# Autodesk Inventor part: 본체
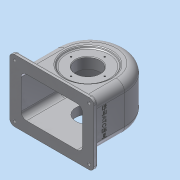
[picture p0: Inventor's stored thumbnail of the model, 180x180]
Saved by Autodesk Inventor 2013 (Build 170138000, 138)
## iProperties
Created: 2016-01
Part Number: 본체
Material: 알루미늄 6061
Document SubType Name: Modeling
Designer: Administrator
Density: 2.71 g/cm^3
Mass: 827.356 g
Surface Area: 1006.17 cm^2
Volume: 305.298 cm^3
Author: Administrator
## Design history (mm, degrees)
sketch "스케치1"
  geometry: L1 (-70, -53)-(70, -53); L2 (70, -53)-(70, -60); L3 (70, -60)-(-70, -60); L4 (-70, -60)-(-70, -53); L5 (-70, -53)-(70, -60); L6 (70, -53)-(-70, -60); L7 (-57, 4)-(-57, -53); L8 (57, 4)-(57, -53); C1 r 51 at (0, 4); A1 r 57 centre (0, 4) between (57, 4) and (-57, 4); 3 further points
  constraints: 16 end point, 3 midpoint, 3 parallel, 2 centre point, 2 perpendicular, 2 point on circle, 2 point on line, 2 tangent, 2 vertical alignment, 1 horizontal
  dimensions: "d0" = 140 distance of L2.end L3.end; "d1" = 7 distance of L1.end L2.end; "d2" = 60 distance from line of point (0, 0) L3; "d3" = 102 diameter of C1; "d4" = 64 distance from line of L3 C1.centre; "d6" = 6 radial gap between concentric circles of C1 A1
extrude "돌출1" new body sketch "스케치1" stored distance "d7" = 77; taper "d8" = 0 deg
extrude "돌출2" join sketch "스케치1" stored distance "d9" = 104; taper "d10" = 0 deg
feature "쉘1" dims "d11" = 6, "d12" = 5
sketch "스케치2"
  geometry: L1 (57, -38.5)-(-57, -38.5) reference; L2 (-57, -38.5)-(-57, 38.5) reference; L3 (-57, 38.5)-(57, 38.5) reference; L4 (57, 38.5)-(57, -38.5) reference; L5 (-51, 33.5)-(-51, -33.5) reference; L6 (-51, -33.5)-(51, -33.5) reference; L7 (51, -33.5)-(51, 33.5) reference; L8 (51, 33.5)-(-51, 33.5) reference; L9 (-51, 33.5)-(51, 33.5); L10 (51, 33.5)-(51, -33.5); L11 (51, -33.5)-(-51, -33.5); L12 (-51, -33.5)-(-51, 33.5); 1 further point
  constraints: 8 end point, 2 parallel, 1 horizontal, 1 perpendicular
extrude "돌출3" cut sketch "스케치2" stored distance "d13" = 10; taper "d14" = 0 deg
sketch "스케치3"
  geometry: C1 r 31 at (0, 0); 1 further point
  constraints: 1 centre point, 1 coincident
  dimensions: "d15" = 62 diameter of C1
extrude "돌출4" join sketch "스케치3" distance "d16" = 10; taper "d17" = 0 deg
hole "구멍1" diameter "d20" = 40; stored, may be unused: countersink angle "d24" = 90 deg, drill point angle "d26" = 0 deg; dims "d18" = 10, "d19" = 10, "d21" = 6, "d22" = 4, "d23" = 2, "d25" = 15
chamfer "모따기1" distance "d27" = 1; stored, may be unused: second distance "d28" = 2, angle "d29" = 45 deg
sketch "스케치4" dims "d30" = 48
  geometry: C1 r 31 at (0, 0) reference; C2 r 21 at (0, 0) reference; 2 further points
  constraints: 2 vertical alignment, 1 coincident, 2 other
hole "구멍2" sketch "스케치4" at (0, 24) diameter "d31" = 2.459; stored, may be unused: countersink angle "d35" = 90 deg, drill point angle "d37" = 118 deg; dims "d32" = 6, "d33" = 4, "d34" = 2, "d36" = 8
fillet "모깎기1" dims "d41" = 14
fillet "모깎기2" dims "d42" = 9
node "작업 평면1"
sketch "스케치5"
  geometry: C1 r 6 at (0, 0); 1 further point
  constraints: 1 centre point, 1 coincident
  dimensions: "d44" = 12 diameter of C1
extrude "돌출5" join sketch "스케치5" stored distance "d45" = 10; taper "d46" = 0 deg
fillet "모깎기3" dims "d47" = 3
hole "구멍3" diameter "d50" = 4.459; stored, may be unused: countersink angle "d54" = 90 deg, drill point angle "d56" = 118 deg; dims "d48" = 10, "d49" = 10, "d51" = 6, "d52" = 4, "d53" = 2, "d55" = 8
fillet "모깎기4" dims "d57" = 8
fillet "모깎기5" dims "d58" = 3
sketch "스케치6"
  geometry: 3 further points
  dimensions: "d59" = 44 vertical distance of point (62, -49) point (0, -5); "d60" = 62 horizontal distance of point (62, -49) point (0, -5); "d61" = 124 distance of point (124, -5) point (0, -5); "d62" = 44 vertical distance of point (124, -5) point (62, -49)
hole "구멍4" sketch "스케치6" at (0, -5), (124, -5) diameter "d63" = 5; stored, may be unused: countersink angle "d67" = 90 deg, drill point angle "d69" = 0 deg; dims "d64" = 6, "d65" = 4, "d66" = 2, "d68" = 7
node "작업 평면2"
sketch "스케치7"
  geometry: C1 r 28 at (0, -4); 1 further point
  constraints: 1 centre point, 1 coincident
  dimensions: "d74" = 56 diameter of C1
extrude "돌출6" join sketch "스케치7" stored distance "d75" = 10; taper "d76" = 40 deg
fillet "모깎기6" dims "d77" = 3
sketch "스케치8"
  geometry: L1 (64, 6)-(67, 6) reference; L2 (67, 6)-(67, 2.229) reference; L3 (67, 2.229)-(55, 2.229) reference; L4 (55, 2.229)-(55, 24.5) reference; L5 (46, 33.5)-(41.426, 33.5) reference; L6 (41.426, 33.5)-(28, 17.5) reference; L7 (28, 17.5)-(-28, 17.5) reference; L8 (-28, 17.5)-(-41.426, 33.5) reference; L9 (-41.426, 33.5)-(-60, 33.5) reference; L10 (-60, 33.5)-(-60, 52) reference; L11 (-60, 52)-(-56, 52) reference; L12 (-53, 49)-(-53, 38.5) reference; L13 (-53, 38.5)-(47, 38.5) reference; L14 (61, 24.5)-(61, 9) reference; L15 (-20, -47.5)-(-21, -48.5) reference; L16 (-21, -48.5)-(-22.771, -48.5) reference; L17 (-22.771, -48.5)-(-22.771, -40.5) reference; L18 (-22.771, -40.5)-(-24, -39.761) reference; L19 (-24, -39.761)-(-25.23, -40.5) reference; L20 (-25.23, -40.5)-(-25.23, -48.5) reference; L21 (-25.23, -48.5)-(-31, -48.5) reference; L22 (-31, -48.5)-(-31, -41.5) reference; L23 (-34, -38.5)-(-53, -38.5) reference; L24 (-53, -38.5)-(-53, -49) reference; L25 (-56, -52)-(-60, -52) reference; L26 (-60, -52)-(-60, -33.5) reference; L27 (-60, -33.5)-(-20, -33.5) reference; L28 (-20, -33.5)-(-20, -47.5) reference; L29 (21, -48.5)-(20, -47.5) reference; L30 (20, -47.5)-(20, -33.5) reference; L31 (20, -33.5)-(46, -33.5) reference; L32 (55, -24.5)-(55, -2.229) reference; L33 (55, -2.229)-(67, -2.229) reference; L34 (67, -2.229)-(67, -6) reference; L35 (67, -6)-(64, -6) reference; L36 (61, -9)-(61, -24.5) reference; L37 (47, -38.5)-(34, -38.5) reference; L38 (31, -41.5)-(31, -48.5) reference; L39 (31, -48.5)-(25.23, -48.5) reference; L40 (25.23, -48.5)-(25.23, -40.5) reference; L41 (25.23, -40.5)-(24, -39.761) reference; L42 (24, -39.761)-(22.771, -40.5) reference; L43 (22.771, -40.5)-(22.771, -48.5) reference; L44 (22.771, -48.5)-(21, -48.5) reference; L45 (39.094, 38.5)-(36.577, 35.5); L46 (36.577, 35.5)-(0, 35.5); L47 (39.094, 38.5)-(0, 38.5); L48 (0, 38.5)-(0, 35.5); A1 r 9 centre (46, 24.5) between (55, 24.5) and (46, 33.5) reference; A2 r 3 centre (-56, 49) between (-53, 49) and (-56, 52) reference; A3 r 14 centre (47, 24.5) between (61, 24.5) and (47, 38.5) reference; A4 r 3 centre (-34, -41.5) between (-31, -41.5) and (-34, -38.5) reference; A5 r 3 centre (-56, -49) between (-56, -52) and (-53, -49) reference; A6 r 9 centre (46, -24.5) between (46, -33.5) and (55, -24.5) reference; A7 r 14 centre (47, -24.5) between (47, -38.5) and (61, -24.5) reference; A8 r 3 centre (34, -41.5) between (34, -38.5) and (31, -41.5) reference; 2 further points
  constraints: 8 end point, 2 parallel, 2 point on line, 1 midpoint, 1 perpendicular, 1 vertical alignment, 2 other
  dimensions: "d78" = 5 distance between parallel lines of L45 L6; "d79" = 3 distance between parallel lines of L13 L46
revolve "회전1" sketch "스케치8" stored, may be unused: angle "d80" = 90 deg
sketch "스케치9"
  geometry: C1 r 36.577 at (0, 0) reference; C2 r 20 at (0, 0)
  constraints: 1 centre point, 1 coincident
  dimensions: "d81" = 40 diameter of C2
extrude "돌출7" cut sketch "스케치9" stored distance "d82" = 10; taper "d83" = 0 deg
sketch "스케치10" dims "d84" = 56
  geometry: C1 r 20 at (0, 0) reference; C2 r 36.577 at (0, 0) reference; 2 further points
  constraints: 2 vertical alignment, 1 coincident, 2 other
hole "구멍5" sketch "스케치10" at (0, 28) diameter "d85" = 2.459; stored, may be unused: countersink angle "d89" = 90 deg, drill point angle "d91" = 118 deg; dims "d86" = 7, "d87" = 4, "d88" = 2, "d90" = 9
chamfer "모따기2" distance "d95" = 1; stored, may be unused: second distance "d96" = 2, angle "d97" = 45 deg
fillet "모깎기7" dims "d98" = 3
chamfer "모따기3" distance "d99" = 1; stored, may be unused: second distance "d100" = 2, angle "d101" = 45 deg
sketch "스케치11"
  geometry: L1 (-63, 57)-(-63, 0) reference; L2 (19.5, -7)-(-68.5, -7) reference; 2 further points
  constraints: 1 other
  dimensions: "d102" = 38.5 distance from line of L1 point (-24.5, 23); "d103" = 30 distance from line of L2 point (-24.5, 23)
feature "엠보싱1" sketch "스케치11" dims "d104" = 0.5, "d105" = 0
fillet "모깎기8" dims "d106" = 1
node "솔리드1"
pattern_circular "원형 패턴1" dims angle "d39" = 360 deg
pattern_linear "직사각형 패턴1" dims "d72" = 88
pattern_circular "원형 패턴2" dims angle "d93" = 360 deg
node "절단 모서리 투영1"
node "절단 모서리 투영2"
other parameters: "d43" = 67, "d73" = 16
